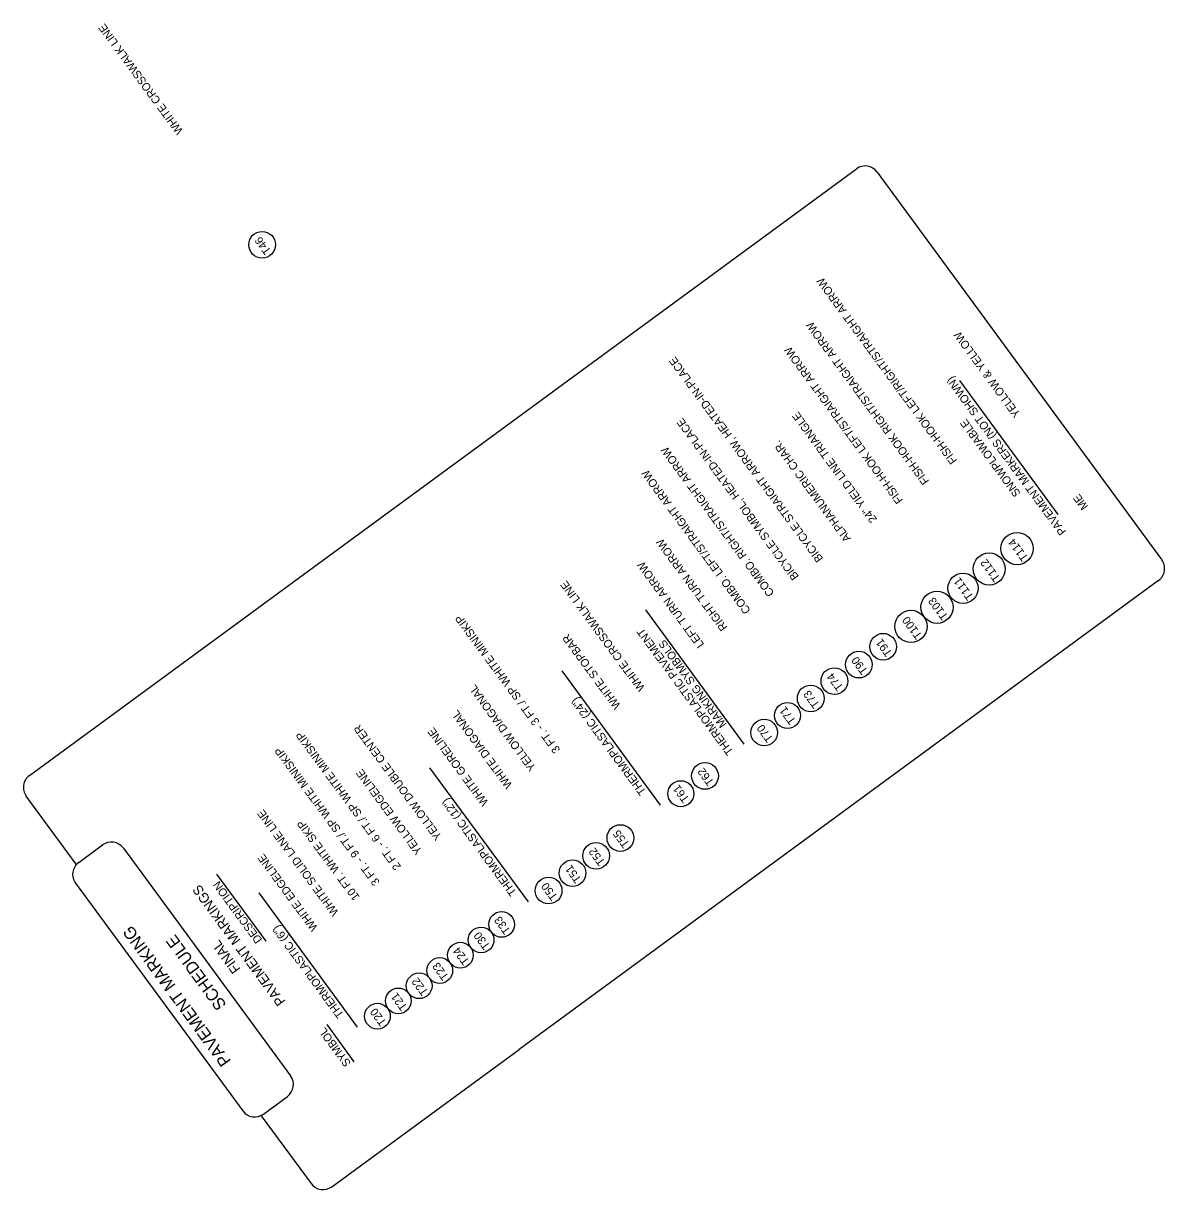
# Model space of a CAD drawing. Extents: x 719153 to 721402, y 581205 to 583188.
# Drawn here: x 720807 to 721402, y 581205 to 581813 of the extents above; entities that cross this region are included whole.
import ezdxf

# ---------------------------------------------------------------- set-up
doc = ezdxf.new("R2010")
doc.units = 0
doc.layers.add('Old_Level_1', color=7, linetype='Continuous')
doc.layers.add('Sheet Sticker Incomplete CELL', color=7, linetype='Continuous')

msp = doc.modelspace()

# ---------------------------------------------------------------- linework, layer by layer
at = {"layer": 'Old_Level_1'}
for centre, radius in [((720931.67, 581697.33), 6.96), ((721325.17, 581538.91), 8.4), ((721310.65, 581528.26), 8.37), ((721297, 581518.23), 7.88), ((721283.45, 581508.28), 8.37), ((721269.87, 581498.32), 8.39), ((721255.39, 581487.71), 6.97), ((721242.69, 581478.39), 6.97), ((721229.95, 581469.81), 6.96), ((721217.62, 581460.77), 6.96), ((721205.5, 581451.87), 6.78), ((721193.38, 581442.98), 6.97), ((721162.53, 581420.35), 6.96), ((721149.92, 581411.1), 6.78), ((721118.42, 581387.98), 6.96), ((721105.76, 581378.7), 6.96), ((721093.47, 581369.68), 6.96), ((721081, 581360.57), 6.96), ((721056.52, 581342.9), 6.7), ((721045.83, 581334.83), 6.7), ((721035.03, 581326.89), 6.7), ((721024.28, 581318.9), 6.7), ((721013.53, 581310.92), 6.7), ((721002.68, 581303.06), 6.7), ((720991.8, 581295.08), 6.7)]:
    msp.add_circle(centre, radius, dxfattribs=at)
at = {"layer": 'Sheet Sticker Incomplete CELL'}
for p, q in [((720810.39, 581420.62), (721241.49, 581736.91)), ((721400.58, 581533.14), (721252.38, 581735.14)), ((721346.58, 581556.6), (721295.32, 581626.57)), ((721398.94, 581522.3), (721065.65, 581277.77)), ((721182.88, 581436.94), (721131.62, 581506.92)), ((721139.4, 581405.09), (721088.14, 581475.07)), ((721070.44, 581354.63), (721019.17, 581424.6)), ((720834.8, 581374.27), (720808.73, 581409.81)), ((720836.07, 581375.19), (720848.54, 581384.34)), ((720859.35, 581382.68), (720946.49, 581263.98)), ((720834.41, 581364.39), (720921.56, 581245.68)), ((720933.77, 581334.15), (720908.08, 581369.21)), ((720981.41, 581289.4), (720930.15, 581359.38)), ((720979.74, 581271.35), (720965.56, 581290.7)), ((720967.98, 581206.11), (721065.65, 581277.77)), ((720932.37, 581244.02), (720944.83, 581253.17)), ((720931.17, 581243.15), (720957.17, 581207.77))]:
    msp.add_line(p, q, dxfattribs=at)
for centre, start, end in [((721246.06, 581730.67), 36.26664, 126.26664), ((721394.37, 581528.53), 306.26669, 36.26669), ((720814.96, 581414.38), 126.26669, 216.26669), ((720853.12, 581378.11), 36.26669, 126.26669), ((720840.65, 581368.96), 126.26669, 216.26669), ((720940.26, 581259.41), 306.26664, 36.26664), ((720927.79, 581250.26), 216.26664, 306.26664), ((720963.41, 581212.35), 216.26664, 306.26664)]:
    msp.add_arc(centre, 7.73, start, end, dxfattribs=at)

# ---------------------------------------------------------------- texts
at = {"layer": 'Old_Level_1'}
for s, height, rotation, p in [('WHITE CROSSWALK LINE', 4.21, 126.22647, (720890.72, 581756.71)), ('T46', 4.21, 126.26667, (720936.62, 581694.13)), ('FISH-HOOK LEFT/RIGHT/STRAIGHT ARROW', 4.21, 126.22647, (721294.11, 581584.8)), ('FISH-HOOK RIGHT/STRAIGHT ARROW', 4.21, 126.22647, (721279.54, 581574.11)), ('YELLOW & YELLOW', 4.21, 126.22647, (721327.13, 581609.13)), ('FISH-HOOK LEFT/STRAIGHT ARROW', 4.21, 126.22647, (721265.96, 581564.15)), ('BICYCLE STRAIGHT ARROW, HEATED-IN-PLACE', 4.21, 126.22647, (721224.31, 581533.65)), ('PAVEMENT MARKERS (NOT SHOWN)', 4.21, 126.22647, (721350.99, 581547.82)), ('BICYCLE SYMBOL, HEATED-IN-PLACE', 4.21, 126.22647, (721211.61, 581524.33)), ('24" YIELD LINE TRIANGLE', 4.21, 126.22647, (721252.38, 581554.2)), ('SNOWPLOWABLE', 4.21, 126.22647, (721327.25, 581567.75)), ('ALPHANUMERIC CHAR.', 4.21, 126.22647, (721238.8, 581544.24)), ('COMBO. RIGHT/STRAIGHT ARROW', 4.21, 126.22647, (721198.86, 581515.76)), ('COMBO. LEFT/STRAIGHT ARROW', 4.21, 126.22647, (721186.54, 581506.71)), ('ME', 4.21, 126.22647, (721362.49, 581560.95)), ('RIGHT TURN ARROW', 4.21, 126.22647, (721174.41, 581497.83)), ('T114', 4.21, 126.26667, (721331.24, 581534.19)), ('LEFT TURN ARROW', 4.21, 126.22647, (721162.28, 581488.94)), ('T112', 4.21, 126.26667, (721316.71, 581523.57)), ('WHITE CROSSWALK LINE', 4.21, 126.22647, (721131.41, 581466.34)), ('T111', 4.21, 126.26667, (721302.76, 581513.94)), ('T103', 4.21, 126.26667, (721289.5, 581503.59)), ('3 FT. - 3 FT./ SP WHITE MINISKIP', 4.21, 126.22647, (721087.28, 581434)), ('T100', 4.21, 126.26667, (721275.94, 581493.61)), ('WHITE STOPBAR', 4.21, 126.22647, (721118.8, 581457.09)), ('THERMOPLASTIC PAVEMENT', 4.21, 126.22647, (721177.58, 581433.06)), ('T91', 4.21, 126.26667, (721260.34, 581484.53)), ('MARKING SYMBOLS', 4.21, 126.22647, (721173.98, 581447.31)), ('T90', 4.21, 126.26667, (721247.64, 581475.21)), ('T74', 4.21, 126.26667, (721234.88, 581466.65)), ('YELLOW DIAGONAL', 4.21, 126.22647, (721074.62, 581424.72)), ('THERMOPLASTIC (24")', 4.21, 126.22647, (721132.05, 581412.23)), ('T73', 4.21, 126.26667, (721222.56, 581457.6)), ('WHITE DIAGONAL', 4.21, 126.22647, (721062.33, 581415.69)), ('T71', 4.21, 126.26667, (721210.14, 581449.11)), ('YELLOW DOUBLE CENTER', 4.21, 126.22647, (721025.57, 581388.77)), ('WHITE GORELINE', 4.21, 126.22647, (721049.86, 581406.59)), ('T70', 4.21, 126.26667, (721198.33, 581439.8)), ('2 FT. - 6 FT./ SP WHITE MINISKIP', 4.21, 126.22647, (721004.27, 581373.14)), ('3 FT. - 9 FT./ SP WHITE MINISKIP', 4.21, 126.22647, (720993.25, 581365.01)), ('T62', 4.21, 126.26667, (721167.46, 581417.18)), ('YELLOW EDGELINE', 4.21, 126.22647, (721015.32, 581381.25)), ('T61', 4.21, 126.26667, (721154.56, 581408.34)), ('THERMOPLASTIC (12")', 4.21, 126.22647, (721064.62, 581359.67)), ('WHITE SOLID LANE LINE ', 4.21, 126.22647, (720971.81, 581349.28)), ('10 FT. WHITE SKIP', 4.21, 126.22647, (720982.72, 581357.28)), ('T55', 4.21, 126.26667, (721123.35, 581384.81)), ('T52', 4.21, 126.26667, (721110.7, 581375.53)), ('WHITE EDGELINE ', 4.21, 126.22647, (720960.9, 581341.28)), ('T51', 4.21, 126.26667, (721098.41, 581366.51)), ('DESCRIPTION', 4.21, 126.22647, (720931.92, 581334.92)), ('T50', 4.21, 126.26667, (721085.95, 581357.39)), ('PAVEMENT MARKINGS', 5.1121, 126.22647, (720944.05, 581302.79)), ('T33', 4.21, 126.26667, (721061.45, 581339.74)), ('THERMOPLASTIC (6")', 4.21, 126.22647, (720974.51, 581295.93)), ('FINAL', 5.112, 126.22647, (720920.61, 581319.65)), ('T30', 4.21, 126.26667, (721050.76, 581331.66)), ('T24', 4.21, 126.26667, (721039.97, 581323.73)), ('T23', 4.21, 126.26667, (721029.22, 581315.74)), ('T22', 4.21, 126.26667, (721018.46, 581307.75)), ('T21', 4.21, 126.26667, (721007.61, 581299.9)), ('T20', 4.21, 126.26667, (720996.73, 581291.92)), ('SYMBOL ', 4.21, 126.22647, (720978.21, 581270.61))]:
    msp.add_text(s, height=height, rotation=rotation, dxfattribs=at).set_placement(p)
at = {"layer": 'Sheet Sticker Incomplete CELL'}
for s, p in [('PAVEMENT MARKING', (720915.71, 581271.73)), ('SCHEDULE', (720913.39, 581301.04))]:
    msp.add_text(s, height=6.315, rotation=126.22647, dxfattribs=at).set_placement(p)

doc.saveas('drawing.dxf')
